// Mitsubishi GX Works2 project: MC-10MR-6MT-F430-FX-B例程   PLC: FX1S

PROGRAM MAIN
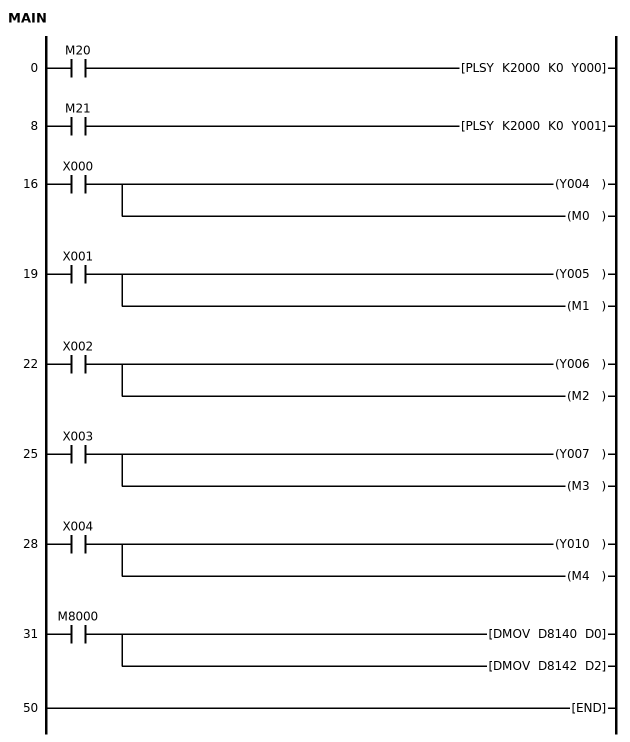
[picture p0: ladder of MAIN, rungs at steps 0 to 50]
0     LD      M20
      PLSY    K2000 K0 Y000
8     LD      M21
      PLSY    K2000 K0 Y001
16    LD      X000
      OUT     Y004
      OUT     M0
19    LD      X001
      OUT     Y005
      OUT     M1
22    LD      X002
      OUT     Y006
      OUT     M2
25    LD      X003
      OUT     Y007
      OUT     M3
28    LD      X004
      OUT     Y010
      OUT     M4
31    LD      M8000
      DMOV    D8140 D0
      DMOV    D8142 D2
50    END
END_PROGRAM
